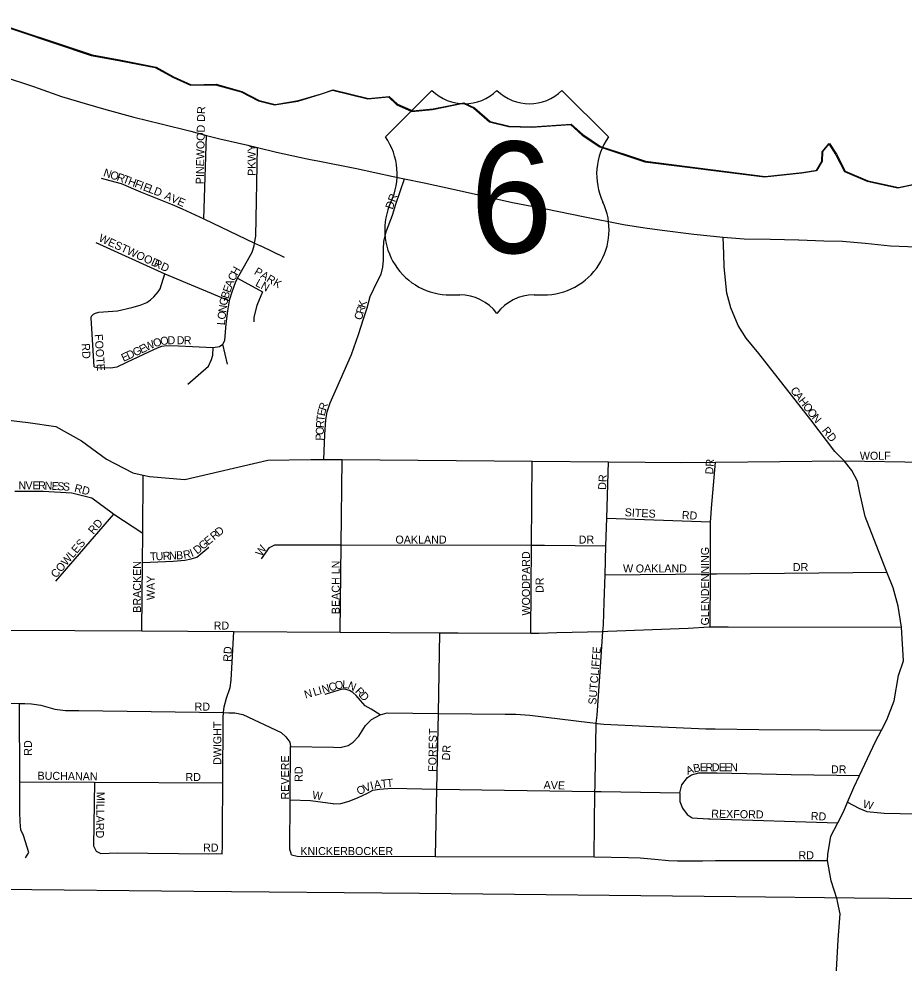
# Model space of a CAD drawing. Extents: x -561 to 1170, y 0 to 846.
# Drawn here: x 56.84 to 71.76, y 265 to 280.92 of the extents above; entities that cross this region are included whole.
import ezdxf

# ---------------------------------------------------------------- set-up
doc = ezdxf.new("R2010")
doc.units = 0
for name, color, linetype in [('GM_X_City_Street', 7, 'Continuous'), ('GM_X_City_Street_Text', 7, 'Continuous'), ('GM_X_County', 7, 'Continuous'), ('GM_X_Major_Lake', 7, 'Continuous'), ('GM_X_Major_River', 7, 'Continuous'), ('GM_X_Rail_Line', 7, 'Continuous'), ('GM_X_US_Location', 7, 'Continuous'), ('GM_X_US_Route', 7, 'Continuous'), ('GM_X_US_Shield', 7, 'Continuous')]:
    doc.layers.add(name, color=color, linetype=linetype)

msp = doc.modelspace()

# ---------------------------------------------------------------- linework, layer by layer
at = {"layer": 'GM_X_City_Street'}
for points in [[(59.956, 277.548), (60.002, 278.955)], [(60.358, 275.099), (60.278, 275.435), (60.311, 275.499), (60.334, 275.781), (60.362, 275.997), (60.388, 276.166), (60.39, 276.176), (60.439, 276.332), (60.489, 276.478), (60.527, 276.549), (60.592, 276.667), (60.772, 276.986), (60.805, 277.094), (60.813, 277.14), (60.833, 277.256), (60.86, 278.75)], [(58.226, 278.236), (58.458, 278.17), (58.561, 278.143), (58.89, 278.006), (59.424, 277.793), (59.592, 277.716)], [(62.992, 277.174), (63.037, 277.347), (63.137, 277.608), (63.195, 277.798), (63.338, 278.223)], [(59.592, 277.716), (59.594, 277.715), (59.956, 277.548), (60.813, 277.14), (60.914, 277.092), (60.916, 277.091)], [(62.198, 274.699), (62.199, 274.702), (62.446, 275.26), (62.562, 275.597), (62.646, 275.864), (62.709, 276.049), (62.761, 276.239), (62.878, 276.489), (62.947, 276.615), (62.973, 276.734), (62.983, 276.853), (62.986, 277.038), (62.99, 277.168), (62.992, 277.174)], [(68.722, 276.961), (68.713, 277.237)], [(70.753, 273.47), (70.597, 273.626), (70.189, 274.16), (69.313, 275.278), (69.101, 275.537), (68.965, 275.748), (68.839, 276.05), (68.774, 276.294), (68.729, 276.738), (68.722, 276.957), (68.713, 277.237)], [(58.135, 277.149), (59.3, 276.619), (60.388, 276.166)], [(60.916, 277.091), (61.312, 276.903)], [(70.753, 273.47), (70.597, 273.626), (70.189, 274.16), (69.313, 275.278), (69.101, 275.537), (68.965, 275.748), (68.839, 276.05), (68.774, 276.294), (68.729, 276.738), (68.722, 276.957), (68.722, 276.961)], [(58.109, 275.054), (58.059, 275.877), (58.065, 275.91), (58.094, 275.939), (58.129, 275.958), (58.184, 275.974), (58.503, 275.999), (58.741, 276.053), (58.882, 276.095), (58.995, 276.138), (59.058, 276.183), (59.115, 276.235), (59.186, 276.32), (59.218, 276.37), (59.3, 276.619)], [(60.527, 276.549), (60.947, 276.319), (60.849, 276.087), (60.799, 275.892), (60.799, 275.811)], [(58.109, 275.054), (58.158, 275.043), (58.385, 275.036), (58.493, 275.052), (58.645, 275.127), (59.04, 275.31), (59.175, 275.374), (59.249, 275.4), (59.332, 275.411), (59.532, 275.405), (60.116, 275.381), (60.219, 275.397), (60.278, 275.435)], [(59.686, 274.76), (60.033, 275.067), (60.088, 275.175), (60.11, 275.251), (60.116, 275.381)], [(61.977, 273.491), (61.994, 273.912), (62.013, 274.162), (62.034, 274.292), (62.086, 274.444), (62.176, 274.651), (62.198, 274.699)], [(56.516, 274.173), (56.998, 274.116), (57.463, 274.046), (57.895, 273.803), (58.317, 273.495), (58.76, 273.268), (58.936, 273.227), (59.041, 273.203), (59.635, 273.155), (61.034, 273.481), (61.763, 273.493), (61.977, 273.491), (62.286, 273.489), (65.491, 273.461), (66.777, 273.451), (68.014, 273.44), (68.582, 273.446), (70.753, 273.47)], [(62.256, 270.58), (62.271, 272.051), (62.286, 273.489)], [(65.472, 270.563), (65.482, 272.045), (65.491, 273.461)], [(66.553, 268.037), (66.554, 268.066), (66.568, 269.026), (66.57, 269.044), (66.585, 269.183), (66.643, 269.995), (66.686, 270.593), (66.694, 270.704), (66.707, 271.083), (66.721, 271.549), (66.735, 272.035), (66.749, 272.501), (66.777, 273.451)], [(68.494, 270.669), (68.498, 271.561), (68.5, 272.028), (68.496, 272.331), (68.5, 272.439), (68.503, 272.504), (68.514, 272.672), (68.582, 273.446)], [(70.639, 266.037), (70.632, 266.071), (70.531, 266.388), (70.468, 266.728), (70.475, 266.83), (70.526, 267.141), (70.643, 267.365), (70.74, 267.549), (70.807, 267.711), (70.914, 267.96), (71.009, 268.165), (71.282, 268.735), (71.382, 268.926), (71.472, 269.099), (71.593, 269.422), (71.667, 269.852), (71.752, 270.098), (71.721, 270.662), (71.661, 271.017), (71.577, 271.329), (71.473, 271.594), (71.251, 272.154), (71.105, 272.529), (71.018, 272.928), (70.974, 273.127), (70.883, 273.303), (70.753, 273.47)], [(70.753, 273.47), (72.12, 273.444), (73.978, 273.408)], [(58.909, 270.601), (58.921, 271.752), (58.926, 272.25), (58.936, 273.227)], [(56.769, 272.957), (57.249, 272.957), (57.73, 272.928), (58.069, 272.843), (58.409, 272.589), (58.44, 272.568), (58.926, 272.25)], [(57.462, 271.44), (58.44, 272.568)], [(66.749, 272.501), (68.5, 272.439)], [(58.921, 271.752), (59.441, 271.775), (59.634, 271.791), (59.742, 271.814), (59.839, 271.842), (60.043, 272.012)], [(60.927, 271.816), (61.063, 272.005), (61.155, 272.053), (61.414, 272.052), (62.271, 272.051), (65.482, 272.045), (65.701, 272.045), (66.735, 272.035)], [(66.721, 271.549), (68.498, 271.561), (68.601, 271.562), (71.473, 271.594)], [(52.28, 270.669), (55.792, 270.626), (56.651, 270.616), (58.909, 270.601), (60.462, 270.592), (62.256, 270.58), (63.937, 270.57), (64.245, 270.568), (65.472, 270.563), (65.602, 270.562), (65.91, 270.572), (66.686, 270.593), (66.77, 270.595), (68.121, 270.649), (68.473, 270.669), (68.494, 270.669), (68.797, 270.668), (71.721, 270.662)], [(60.266, 266.844), (60.272, 266.979), (60.274, 267.266), (60.277, 268.04), (60.282, 269.139), (60.29, 269.223), (60.299, 269.323), (60.338, 269.469), (60.398, 269.647), (60.415, 269.772), (60.462, 270.592)], [(63.872, 267.377), (63.884, 267.935), (63.91, 269.211), (63.937, 270.57)], [(62.931, 269.187), (62.78, 269.28), (62.678, 269.34), (62.597, 269.427), (62.525, 269.514), (62.47, 269.564), (62.414, 269.596), (62.353, 269.613), (62.29, 269.618), (61.997, 269.527)], [(56.186, 269.389), (56.851, 269.376), (56.937, 269.375), (57.051, 269.374), (57.208, 269.347), (57.445, 269.281), (57.622, 269.257), (57.85, 269.257), (60.29, 269.223), (60.379, 269.221), (60.481, 269.221), (60.612, 269.192), (61.259, 268.886), (61.34, 268.815), (61.405, 268.723), (61.42, 268.652), (62.145, 268.639), (62.259, 268.638), (62.299, 268.648)], [(56.953, 266.776), (57.007, 266.863), (56.916, 267.15), (56.874, 267.248), (56.863, 267.383), (56.853, 267.551), (56.853, 268.054), (56.851, 269.376)], [(62.299, 268.648), (62.302, 268.649), (62.388, 268.67), (62.475, 268.724), (62.567, 268.826), (62.681, 269.004), (62.785, 269.107), (62.931, 269.187), (63.045, 269.219), (63.91, 269.211), (65.034, 269.2), (65.217, 269.2), (65.455, 269.182), (66.465, 269.054), (66.57, 269.044), (66.586, 269.042)], [(66.586, 269.042), (66.588, 269.042), (66.698, 269.031), (67.411, 268.996), (68.297, 268.954), (68.418, 268.951)], [(68.418, 268.951), (68.424, 268.951), (68.578, 268.948), (69.313, 268.939), (71.382, 268.926)], [(61.434, 266.828), (61.407, 266.92), (61.414, 267.754), (61.42, 268.652)], [(67.979, 267.873), (68.017, 268.008), (68.11, 268.132), (68.18, 268.175), (68.299, 268.207), (68.467, 268.206)], [(68.467, 268.206), (68.469, 268.206), (68.613, 268.206), (69.861, 268.179), (71.009, 268.165)], [(56.853, 268.054), (58.115, 268.049), (60.277, 268.04)], [(58.115, 268.049), (58.099, 266.977), (58.142, 266.89), (58.218, 266.847), (58.504, 266.857), (60.039, 266.845), (60.164, 266.85), (60.266, 266.844)], [(62.131, 267.689), (62.151, 267.686), (62.265, 267.691), (62.405, 267.728), (62.557, 267.792), (62.703, 267.857), (62.806, 267.916), (62.92, 267.932), (63.125, 267.947), (63.884, 267.935), (66.551, 267.895)], [(66.536, 266.791), (66.551, 267.895), (66.552, 267.982), (66.553, 268.037)], [(66.551, 267.895), (66.655, 267.893), (67.979, 267.873)], [(67.979, 267.873), (67.984, 267.727), (68.026, 267.613), (68.107, 267.504), (68.188, 267.45), (68.463, 267.432), (68.49, 267.431), (68.493, 267.431)], [(61.414, 267.754), (61.757, 267.742), (62.131, 267.689)], [(70.807, 267.711), (70.999, 267.611), (71.134, 267.557), (71.426, 267.528), (71.966, 267.517), (73.236, 267.483), (73.872, 267.464)], [(63.861, 266.796), (63.872, 267.377), (63.872, 267.377)], [(68.493, 267.431), (70.643, 267.365)], [(61.434, 266.828), (61.531, 266.801), (63.861, 266.796), (66.536, 266.791), (67.114, 266.783), (67.314, 266.777), (67.558, 266.754), (67.79, 266.731), (67.941, 266.725), (68.184, 266.724), (68.36, 266.726)], [(68.36, 266.726), (68.364, 266.726), (68.584, 266.728), (70.468, 266.728)], [(67.356, 258.234), (67.414, 258.319), (67.893, 258.804), (68.214, 259.117), (68.384, 259.22), (68.543, 259.344), (68.75, 259.485), (69.037, 259.672), (69.293, 259.826), (69.509, 260.017), (69.78, 260.193), (69.999, 260.291), (70.137, 260.393), (70.232, 260.477), (70.289, 260.549), (70.369, 260.974), (70.619, 264.781), (70.651, 265.394), (70.682, 265.829), (70.639, 266.037)]]:
    msp.add_lwpolyline(points, dxfattribs=at)
at = {"layer": 'GM_X_County'}
msp.add_lwpolyline([(56.231, 280.913), (58.06, 280.304), (58.554, 280.214), (59.139, 280.098), (59.433, 279.937), (59.731, 279.803), (60.154, 279.81), (60.588, 279.688), (60.876, 279.537), (61.147, 279.468), (61.542, 279.535), (61.926, 279.651), (62.126, 279.717), (62.723, 279.573), (63.07, 279.607), (63.211, 279.473), (63.466, 279.36), (63.813, 279.394), (64.327, 279.5), (64.506, 279.414), (64.773, 279.182), (65.093, 279.103), (65.483, 279.094), (66.138, 279.14), (66.334, 278.962), (66.633, 278.763), (67.056, 278.624), (67.393, 278.512), (69.41, 278.256), (70.038, 278.324), (70.287, 278.363), (70.373, 278.516), (70.383, 278.678), (70.491, 278.814), (70.611, 278.63), (70.758, 278.344), (71.138, 278.183), (71.659, 278.072), (72.184, 278.183)], dxfattribs=at)
at = {"layer": 'GM_X_Major_Lake'}
msp.add_lwpolyline([(56.243, 280.92), (58.072, 280.311), (58.565, 280.221), (59.151, 280.105), (59.444, 279.944), (59.743, 279.81), (60.165, 279.817), (60.599, 279.695), (60.887, 279.544), (61.158, 279.475), (61.554, 279.542), (61.938, 279.658), (62.138, 279.724), (62.734, 279.58), (63.081, 279.614), (63.223, 279.48), (63.478, 279.367), (63.824, 279.401), (64.339, 279.507), (64.518, 279.421), (64.784, 279.189), (65.104, 279.109), (65.494, 279.1), (66.15, 279.147), (66.346, 278.969), (66.645, 278.77), (67.068, 278.631), (67.404, 278.519), (69.421, 278.263), (70.049, 278.331), (70.298, 278.37), (70.384, 278.522), (70.394, 278.685), (70.502, 278.821), (70.622, 278.637), (70.77, 278.351), (71.15, 278.19), (71.67, 278.079), (72.195, 278.19)], dxfattribs=at)
msp.add_lwpolyline([(56.243, 280.92), (58.072, 280.311), (58.565, 280.221), (59.151, 280.105), (59.444, 279.944), (59.743, 279.81), (60.165, 279.817), (60.599, 279.695), (60.887, 279.544), (61.158, 279.475), (61.554, 279.542), (61.938, 279.658), (62.138, 279.724), (62.734, 279.58), (63.081, 279.614), (63.223, 279.48), (63.478, 279.367), (63.824, 279.401), (64.339, 279.507), (64.518, 279.421), (64.784, 279.189), (65.104, 279.109), (65.494, 279.1), (66.15, 279.147), (66.346, 278.969), (66.645, 278.77), (67.068, 278.631), (67.404, 278.519), (69.421, 278.263), (70.049, 278.331), (70.298, 278.37), (70.384, 278.522), (70.394, 278.685), (70.502, 278.821), (70.622, 278.637), (70.77, 278.351), (71.15, 278.19), (71.67, 278.079), (72.195, 278.19)], dxfattribs=at)
at = {"layer": 'GM_X_Major_River'}
msp.add_lwpolyline([(56.243, 280.92), (58.072, 280.311), (58.565, 280.221), (59.151, 280.105), (59.444, 279.944), (59.743, 279.81), (60.165, 279.817), (60.599, 279.695), (60.887, 279.544), (61.158, 279.475), (61.554, 279.542), (61.938, 279.658), (62.138, 279.724), (62.734, 279.58), (63.081, 279.614), (63.223, 279.48), (63.478, 279.367), (63.824, 279.401), (64.339, 279.507), (64.518, 279.421), (64.784, 279.189), (65.104, 279.109), (65.494, 279.1), (66.15, 279.147), (66.346, 278.969), (66.645, 278.77), (67.068, 278.631), (67.404, 278.519), (69.421, 278.263), (70.049, 278.331), (70.298, 278.37), (70.384, 278.522), (70.394, 278.685), (70.502, 278.821), (70.622, 278.637), (70.77, 278.351), (71.15, 278.19), (71.67, 278.079), (72.195, 278.19)], dxfattribs=at)
at = {"layer": 'GM_X_Rail_Line'}
msp.add_lwpolyline([(38.104, 266.374), (46.926, 266.33), (48.807, 266.32), (50.698, 266.304), (52.237, 266.285), (56.506, 266.247), (59.789, 266.214), (63.592, 266.177), (68.925, 266.123), (70.922, 266.1), (73.902, 266.071), (82.475, 265.99), (88.766, 265.928)], dxfattribs=at)
at = {"layer": 'GM_X_US_Route'}
for points in [[(56.576, 279.947), (57.085, 279.779), (57.555, 279.611), (57.956, 279.492), (58.307, 279.394), (58.778, 279.264), (59.237, 279.151), (59.735, 279.026), (60.002, 278.955), (60.227, 278.896), (60.698, 278.788), (60.86, 278.75), (61.184, 278.674), (61.699, 278.562), (61.785, 278.544), (61.88, 278.525)], [(61.88, 278.525), (62.531, 278.397), (63.148, 278.262), (63.338, 278.223), (63.672, 278.153), (64.159, 278.051), (64.635, 277.942), (65.16, 277.823), (65.722, 277.715), (66.349, 277.59), (67.031, 277.454), (67.393, 277.395), (67.685, 277.357), (68.215, 277.292), (68.713, 277.237), (69.065, 277.21), (69.508, 277.205), (69.984, 277.194), (69.988, 277.194)], [(69.988, 277.194), (70.411, 277.177), (70.725, 277.172), (71.104, 277.139), (71.531, 277.096), (72.115, 277.069), (72.508, 277.017), (72.533, 277.013)]]:
    msp.add_lwpolyline(points, dxfattribs=at)
at = {"layer": 'GM_X_US_Shield'}
for p, q in [((63.801, 279.713), (63.018, 278.93)), ((66.777, 278.93), (65.994, 279.713)), ((64.115, 276.267), (64.271, 276.267)), ((65.524, 276.267), (65.681, 276.267))]:
    msp.add_line(p, q, dxfattribs=at)
for centre, radius, start, end in [((64.35, 280.272), 0.783, 225.573, 314.427), ((65.446, 280.272), 0.783, 225.573, 314.427), ((62.12, 278.301), 1.096, 334.5471, 35.0009), ((67.675, 278.301), 1.096, 144.9991, 205.4529), ((64.102, 277.364), 1.096, 154.8319, 270.6383), ((65.693, 277.364), 1.096, 269.3617, 25.1681), ((64.271, 275.484), 0.783, 36.8699, 90), ((65.524, 275.484), 0.783, 90, 143.1301)]:
    msp.add_arc(centre, radius, start, end, dxfattribs=at)

# ---------------------------------------------------------------- texts
at = {"layer": 'GM_X_City_Street_Text'}
for s, rotation, p in [('PINEWOOD DR', 88.8183, (59.954, 278.131)), ('PKWY', 90, (60.833, 278.273)), ('N', 341.5409, (58.253, 278.273)), ('O', 341.5201, (58.366, 278.236)), ('R', 341.0544, (58.478, 278.198)), ('T', 339.5687, (58.578, 278.164)), ('H', 339.1241, (58.667, 278.13)), ('F', 339.1018, (58.778, 278.088)), ('I', 339.0833, (58.867, 278.054)), ('E', 339.1204, (58.922, 278.033)), ('L', 339.1018, (59.011, 277.999)), ('D', 339.0936, (59.1, 277.965)), ('AVE', 336.0337, (59.278, 277.892)), ('DR', 70.7095, (63.139, 277.698)), ('WESTWOOD', 335.3227, (58.172, 277.179)), ('RD', 336.0409, (59.099, 276.752)), ('H', 60.5696, (60.519, 276.582)), ('PARK', 329.2986, (60.794, 276.624)), ('C', 62.3489, (60.47, 276.488)), ('LN', 332.106, (60.815, 276.425)), ('E', 70.7138, (60.399, 276.292)), ('A', 69.201, (60.43, 276.381)), ('G', 80.0167, (60.347, 276.079)), ('B', 72.4214, (60.367, 276.191)), ('N', 82.9102, (60.333, 275.962)), ('R', 73.8078, (62.646, 275.935)), ('K', 73.81, (62.676, 276.038)), ('O', 83.1216, (60.319, 275.845)), ('C', 73.8194, (62.616, 275.832)), ('L', 84.8983, (60.31, 275.751)), ('FOOTE', 273.8142, (58.116, 275.601)), ('RD', 273.0167, (57.898, 275.446)), ('E', 24.9501, (58.904, 275.276)), ('W', 24.9595, (58.99, 275.316)), ('O', 18.5283, (59.126, 275.38)), ('O', 8.8425, (59.233, 275.416)), ('D', 0.5682, (59.345, 275.434)), ('D', 0, (59.499, 275.435)), ('R', 0, (59.618, 275.435)), ('E', 24.9583, (58.602, 275.136)), ('D', 24.9568, (58.688, 275.176)), ('G', 24.9522, (58.796, 275.226)), ('C', 307.7781, (69.836, 274.653)), ('A', 307.7873, (69.902, 274.569)), ('H', 307.8031, (69.974, 274.475)), ('E', 78.2963, (61.995, 274.216)), ('R', 72.4098, (62.014, 274.305)), ('O', 307.7878, (70.047, 274.381)), ('O', 308.0344, (70.12, 274.286)), ('R', 87.8021, (61.982, 274.02)), ('T', 83.8272, (61.986, 274.125)), ('N', 309.9503, (70.197, 274.189)), ('O', 87.8085, (61.977, 273.902)), ('RD', 308.6563, (70.37, 273.976)), ('P', 87.8142, (61.974, 273.807)), ('WOLF', 0, (71.016, 273.487)), ('DR', 86.8155, (68.543, 273.237)), ('DR', 86.9827, (66.737, 272.976)), ('N', 359.9758, (56.831, 272.988)), ('V', 359.9758, (56.95, 272.988)), ('E', 359.9727, (57.069, 272.988)), ('R', 359.1014, (57.163, 272.988)), ('N', 357.2233, (57.269, 272.986)), ('E', 356.8838, (57.388, 272.98)), ('S', 356.9172, (57.483, 272.975)), ('S', 356.9111, (57.577, 272.97)), ('RD', 345.2542, (57.764, 272.951)), ('SITES', 356.9077, (67.049, 272.536)), ('RD', 356.9887, (68.012, 272.489)), ('RD', 49.4006, (58.095, 272.219)), ('R', 39.6684, (60.131, 272.123)), ('D', 39.6792, (60.213, 272.191)), ('COWLES', 49.9418, (57.465, 271.482)), ('G', 39.6792, (59.939, 271.963)), ('E', 39.6709, (60.03, 272.039)), ('OAKLAND', 0, (63.187, 272.073)), ('DR', 0, (66.276, 272.073)), ('T', 2.4872, (59.052, 271.788)), ('U', 2.4706, (59.147, 271.792)), ('R', 2.4694, (59.266, 271.797)), ('N', 2.4706, (59.373, 271.802)), ('B', 2.4694, (59.492, 271.807)), ('R', 11.4382, (59.621, 271.814)), ('I', 22.1643, (59.753, 271.844)), ('D', 38.6419, (59.844, 271.887)), ('W', 57.5237, (60.932, 271.847)), ('WOODPARD', 90, (65.454, 270.86)), ('GLENDENNING', 90, (68.472, 270.693)), ('BRACKEN', 90, (58.897, 270.907)), ('BEACH LN', 90, (62.247, 270.883)), ('W', 0, (67.024, 271.586)), ('OAKLAND', 0, (67.238, 271.586)), ('DR', 0, (69.887, 271.61)), ('WAY', 90, (59.129, 271.121)), ('DR', 90, (65.684, 271.24)), ('RD', 0, (60.122, 270.624)), ('RD', 86.9827, (60.417, 270.077)), ('SUTCLIFFE', 85.3633, (66.571, 269.353)), ('N', 16.2091, (61.968, 269.545)), ('C', 16.2189, (62.082, 269.578)), ('O', 13.8613, (62.183, 269.607)), ('L', 358.0599, (62.289, 269.635)), ('N', 336.9851, (62.371, 269.634)), ('N', 16.1916, (61.671, 269.458)), ('L', 16.1968, (61.819, 269.502)), ('I', 16.1736, (61.911, 269.528)), ('R', 314.4934, (62.497, 269.574)), ('D', 312.4567, (62.571, 269.499)), ('RD', 0, (59.801, 269.257)), ('DWIGHT', 90, (60.251, 268.341)), ('FOREST', 88.8989, (63.874, 268.223)), ('RD', 90, (57.059, 268.496)), ('DR', 86.9884, (64.104, 268.414)), ('REVERE', 90, (61.392, 267.759)), ('RD', 90, (61.621, 268.056)), ('A', 21.4565, (68.115, 268.172)), ('B', 10.6003, (68.219, 268.214)), ('E', 1.612, (68.319, 268.233)), ('R', 0, (68.413, 268.235)), ('D', 0, (68.52, 268.235)), ('E', 0, (68.638, 268.235)), ('E', 0, (68.733, 268.235)), ('N', 0, (68.828, 268.235)), ('DR', 0, (70.529, 268.2)), ('BUCHANAN', 359.2752, (57.152, 268.093)), ('RD', 0, (59.647, 268.07)), ('T', 5.9661, (62.95, 267.955)), ('T', 5.0881, (63.044, 267.965)), ('O', 25.0301, (62.57, 267.829)), ('V', 23.6607, (62.677, 267.879)), ('I', 15.0807, (62.781, 267.925)), ('A', 7.2985, (62.833, 267.94)), ('AVE', 358.0262, (65.683, 267.939)), ('MILLARD', 269.0911, (58.15, 267.889)), ('W', 351.2589, (61.777, 267.772)), ('W', 345.8007, (71.058, 267.625)), ('REXFORD', 359.1191, (68.51, 267.452)), ('RD', 356.989, (70.186, 267.416)), ('RD', 0, (59.944, 266.88)), ('KNICKERBOCKER', 0, (61.583, 266.822)), ('RD', 0, (69.982, 266.751))]:
    msp.add_text(s, height=0.135, rotation=rotation, dxfattribs=at).set_placement(p)
at = {"layer": 'GM_X_US_Location'}
for s in ['0', '/']:
    msp.add_text(s, height=0.0027, dxfattribs=at).set_placement((64.897, 277.897))
msp.add_text('6', height=0.0027, rotation=0, dxfattribs=at).set_placement((64.624, 277.338))
at = {"layer": 'GM_X_US_Shield'}
msp.add_text('6', height=1.879, dxfattribs=at).set_placement((64.443, 276.972))

doc.saveas('drawing.dxf')
